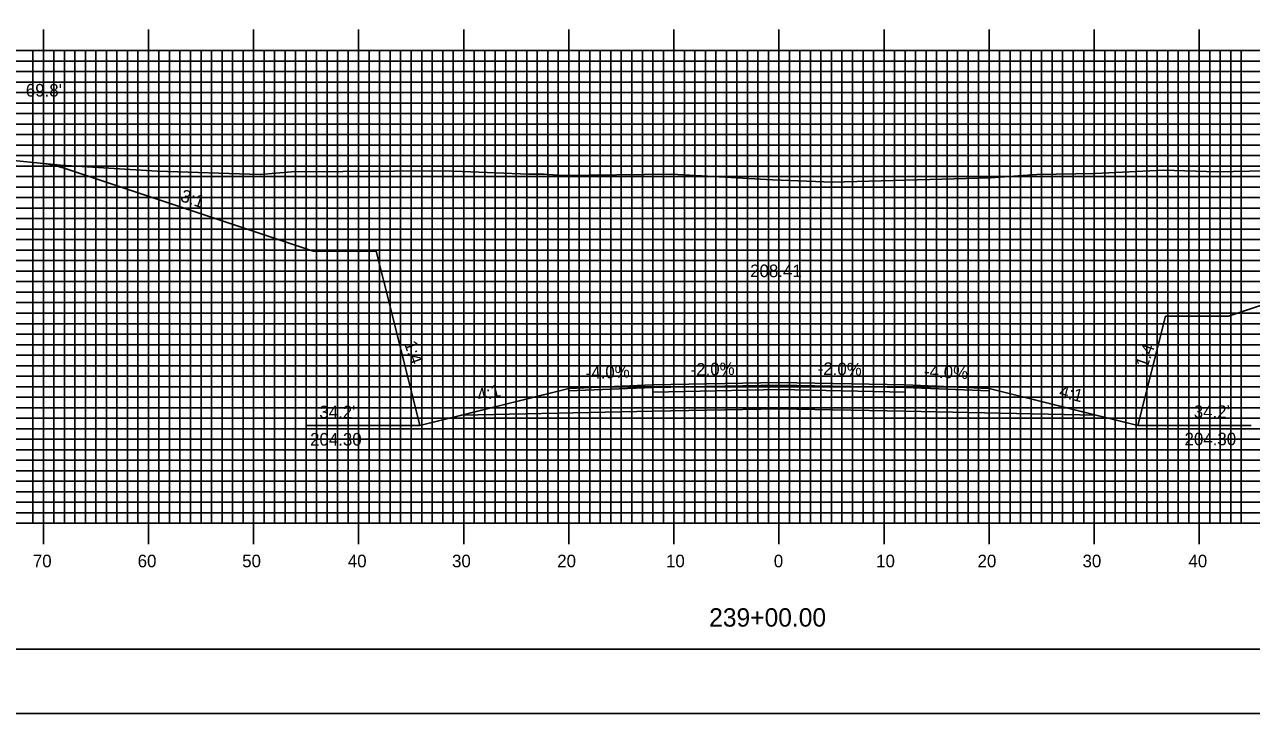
# Model space of a CAD drawing. Extents: x 1801536 to 1801879, y 442591 to 442811.
# Drawn here: x 1801629.8 to 1801746.5, y 442590.5 to 442656.2 of the extents above; entities that cross this region are included whole.
import ezdxf

# ---------------------------------------------------------------- set-up
doc = ezdxf.new("R2010")
doc.units = 0
for name, color, linetype in [('ANNOTATION', 7, 'Continuous'), ('BORDER', 7, 'Continuous'), ('D_Roadway_Centerline', 7, 'Continuous'), ('D_Roadway_Centerline_Text', 7, 'Continuous'), ('D_Roadway_Edge_Shoulder', 7, 'Continuous'), ('D_Roadway_Edge_TW', 7, 'Continuous'), ('D_Roadway_Pavement', 7, 'Continuous'), ('D_Roadway_SlopeLines', 7, 'Continuous'), ('D_Roadway_SubGrade', 7, 'Continuous'), ('D_Text_Standard', 7, 'Continuous'), ('H_V ANNOTATION', 7, 'Continuous'), ('MAJOR', 7, 'Continuous'), ('MINOR', 7, 'Continuous'), ('PDRAIN', 7, 'Continuous'), ('PLOT BOUNDARY', 7, 'Continuous'), ('S_Roadway_Centerline', 7, 'Continuous')]:
    doc.layers.add(name, color=color, linetype=linetype)

msp = doc.modelspace()

# ---------------------------------------------------------------- linework, layer by layer
at = {"layer": 'ANNOTATION'}
for p, q in [((1801735.75, 442617.97), (1801738.36, 442628.39)), ((1801738.36, 442628.39), (1801744.36, 442628.39))]:
    msp.add_line(p, q, dxfattribs=at)
at = {"layer": 'BORDER'}
msp.add_lwpolyline([(1801551.98, 442596.67), (1801871.98, 442596.67), (1801871.98, 442806.67), (1801551.98, 442806.67)], close=True, dxfattribs=at)
at = {"layer": 'D_Roadway_Centerline'}
msp.add_lwpolyline([(1801667.4, 442617.97), (1801671.4, 442618.97), (1801681.58, 442621.51), (1801689.58, 442621.83), (1801701.58, 442622.07), (1801713.58, 442621.83), (1801721.58, 442621.51), (1801731.75, 442618.97), (1801735.75, 442617.97)], dxfattribs=at)
at = {"layer": 'D_Roadway_Edge_Shoulder'}
for points in [[(1801689.58, 442621.83), (1801681.58, 442621.51), (1801681.58, 442621.26), (1801689.58, 442621.58)], [(1801713.58, 442621.83), (1801721.58, 442621.51), (1801721.58, 442621.26), (1801713.58, 442621.58)]]:
    msp.add_lwpolyline(points, close=True, dxfattribs=at)
at = {"layer": 'D_Roadway_Edge_TW'}
msp.add_lwpolyline([(1801689.58, 442621.58), (1801689.58, 442621.83), (1801701.58, 442622.07), (1801713.58, 442621.83), (1801713.58, 442621.58), (1801701.58, 442621.82)], close=True, dxfattribs=at)
at = {"layer": 'D_Roadway_Pavement'}
msp.add_lwpolyline([(1801689.58, 442621.16), (1801689.58, 442621.58), (1801701.58, 442621.82), (1801713.58, 442621.58), (1801713.58, 442621.16), (1801701.58, 442621.4)], close=True, dxfattribs=at)
at = {"layer": 'D_Roadway_SlopeLines'}
for p, q in [((1801781.97, 442640.93), (1801744.36, 442628.39)), ((1801667.4, 442617.97), (1801664.6, 442629.18))]:
    msp.add_line(p, q, dxfattribs=at)
for points in [[(1801664.6, 442629.18), (1801663.25, 442634.57), (1801657.25, 442634.57), (1801633.55, 442642.47)], [(1801681.58, 442621.51), (1801667.4, 442617.97)], [(1801721.58, 442621.51), (1801735.75, 442617.97)]]:
    msp.add_lwpolyline(points, dxfattribs=at)
msp.add_arc((1801629.88, 442631.45), 11.62, 71.5651, 80.3898, dxfattribs=at)
at = {"layer": 'D_Roadway_SubGrade'}
msp.add_lwpolyline([(1801689.58, 442619.33), (1801671.4, 442618.97), (1801681.58, 442621.51), (1801681.58, 442621.26), (1801689.58, 442621.58), (1801701.58, 442621.82), (1801713.58, 442621.58), (1801721.58, 442621.26), (1801721.58, 442621.51), (1801731.75, 442618.97), (1801713.58, 442619.33), (1801701.58, 442619.57)], close=True, dxfattribs=at)
at = {"layer": 'MAJOR'}
for p, q in [((1801631.58, 442655.67), (1801631.58, 442653.67)), ((1801641.58, 442655.67), (1801641.58, 442653.67)), ((1801651.58, 442655.67), (1801651.58, 442653.67)), ((1801661.58, 442655.67), (1801661.58, 442653.67)), ((1801671.58, 442655.67), (1801671.58, 442653.67)), ((1801681.58, 442655.67), (1801681.58, 442653.67)), ((1801691.58, 442655.67), (1801691.58, 442653.67)), ((1801701.58, 442655.67), (1801701.58, 442653.67)), ((1801711.58, 442655.67), (1801711.58, 442653.67)), ((1801721.58, 442655.67), (1801721.58, 442653.67)), ((1801731.58, 442655.67), (1801731.58, 442653.67)), ((1801741.58, 442655.67), (1801741.58, 442653.67)), ((1801561.58, 442653.67), (1801841.58, 442653.67)), ((1801561.58, 442653.67), (1801841.58, 442653.67)), ((1801631.58, 442608.67), (1801631.58, 442653.67)), ((1801641.58, 442608.67), (1801641.58, 442653.67)), ((1801651.58, 442608.67), (1801651.58, 442653.67)), ((1801661.58, 442608.67), (1801661.58, 442653.67)), ((1801671.58, 442608.67), (1801671.58, 442653.67)), ((1801681.58, 442608.67), (1801681.58, 442653.67)), ((1801691.58, 442608.67), (1801691.58, 442653.67)), ((1801701.58, 442608.67), (1801701.58, 442653.67)), ((1801711.58, 442608.67), (1801711.58, 442653.67)), ((1801721.58, 442608.67), (1801721.58, 442653.67)), ((1801731.58, 442608.67), (1801731.58, 442653.67)), ((1801741.58, 442608.67), (1801741.58, 442653.67)), ((1801561.58, 442648.67), (1801841.58, 442648.67)), ((1801561.58, 442643.67), (1801841.58, 442643.67)), ((1801561.58, 442638.67), (1801841.58, 442638.67)), ((1801561.58, 442633.67), (1801841.58, 442633.67)), ((1801561.58, 442628.67), (1801841.58, 442628.67)), ((1801561.58, 442623.67), (1801841.58, 442623.67)), ((1801561.58, 442618.67), (1801841.58, 442618.67)), ((1801561.58, 442613.67), (1801841.58, 442613.67)), ((1801561.58, 442608.67), (1801841.58, 442608.67)), ((1801561.58, 442608.67), (1801841.58, 442608.67)), ((1801631.58, 442606.66), (1801631.58, 442608.67)), ((1801641.58, 442606.66), (1801641.58, 442608.67)), ((1801651.58, 442606.66), (1801651.58, 442608.67)), ((1801661.58, 442606.66), (1801661.58, 442608.67)), ((1801671.58, 442606.66), (1801671.58, 442608.67)), ((1801681.58, 442606.66), (1801681.58, 442608.67)), ((1801691.58, 442606.66), (1801691.58, 442608.67)), ((1801701.58, 442606.66), (1801701.58, 442608.67)), ((1801711.58, 442606.66), (1801711.58, 442608.67)), ((1801721.58, 442606.66), (1801721.58, 442608.67)), ((1801731.58, 442606.66), (1801731.58, 442608.67)), ((1801741.58, 442606.66), (1801741.58, 442608.67))]:
    msp.add_line(p, q, dxfattribs=at)
at = {"layer": 'MINOR'}
for p, q in [((1801630.58, 442608.67), (1801630.58, 442653.67)), ((1801632.58, 442608.67), (1801632.58, 442653.67)), ((1801633.58, 442608.67), (1801633.58, 442653.67)), ((1801634.58, 442608.67), (1801634.58, 442653.67)), ((1801635.58, 442608.67), (1801635.58, 442653.67)), ((1801636.58, 442608.67), (1801636.58, 442653.67)), ((1801637.58, 442608.67), (1801637.58, 442653.67)), ((1801638.58, 442608.67), (1801638.58, 442653.67)), ((1801639.58, 442608.67), (1801639.58, 442653.67)), ((1801640.58, 442608.67), (1801640.58, 442653.67)), ((1801642.58, 442608.67), (1801642.58, 442653.67)), ((1801643.58, 442608.67), (1801643.58, 442653.67)), ((1801644.58, 442608.67), (1801644.58, 442653.67)), ((1801645.58, 442608.67), (1801645.58, 442653.67)), ((1801646.58, 442608.67), (1801646.58, 442653.67)), ((1801647.58, 442608.67), (1801647.58, 442653.67)), ((1801648.58, 442608.67), (1801648.58, 442653.67)), ((1801649.58, 442608.67), (1801649.58, 442653.67)), ((1801650.58, 442608.67), (1801650.58, 442653.67)), ((1801652.58, 442608.67), (1801652.58, 442653.67)), ((1801653.58, 442608.67), (1801653.58, 442653.67)), ((1801654.58, 442608.67), (1801654.58, 442653.67)), ((1801655.58, 442608.67), (1801655.58, 442653.67)), ((1801656.58, 442608.67), (1801656.58, 442653.67)), ((1801657.58, 442608.67), (1801657.58, 442653.67)), ((1801658.58, 442608.67), (1801658.58, 442653.67)), ((1801659.58, 442608.67), (1801659.58, 442653.67)), ((1801660.58, 442608.67), (1801660.58, 442653.67)), ((1801662.58, 442608.67), (1801662.58, 442653.67)), ((1801663.58, 442608.67), (1801663.58, 442653.67)), ((1801664.58, 442608.67), (1801664.58, 442653.67)), ((1801665.58, 442608.67), (1801665.58, 442653.67)), ((1801666.58, 442608.67), (1801666.58, 442653.67)), ((1801667.58, 442608.67), (1801667.58, 442653.67)), ((1801668.58, 442608.67), (1801668.58, 442653.67)), ((1801669.58, 442608.67), (1801669.58, 442653.67)), ((1801670.58, 442608.67), (1801670.58, 442653.67)), ((1801672.58, 442608.67), (1801672.58, 442653.67)), ((1801673.58, 442608.67), (1801673.58, 442653.67)), ((1801674.58, 442608.67), (1801674.58, 442653.67)), ((1801675.58, 442608.67), (1801675.58, 442653.67)), ((1801676.58, 442608.67), (1801676.58, 442653.67)), ((1801677.58, 442608.67), (1801677.58, 442653.67)), ((1801678.58, 442608.67), (1801678.58, 442653.67)), ((1801679.58, 442608.67), (1801679.58, 442653.67)), ((1801680.58, 442608.67), (1801680.58, 442653.67)), ((1801682.58, 442608.67), (1801682.58, 442653.67)), ((1801683.58, 442608.67), (1801683.58, 442653.67)), ((1801684.58, 442608.67), (1801684.58, 442653.67)), ((1801685.58, 442608.67), (1801685.58, 442653.67)), ((1801686.58, 442608.67), (1801686.58, 442653.67)), ((1801687.58, 442608.67), (1801687.58, 442653.67)), ((1801688.58, 442608.67), (1801688.58, 442653.67)), ((1801689.58, 442608.67), (1801689.58, 442653.67)), ((1801690.58, 442608.67), (1801690.58, 442653.67)), ((1801692.58, 442608.67), (1801692.58, 442653.67)), ((1801693.58, 442608.67), (1801693.58, 442653.67)), ((1801694.58, 442608.67), (1801694.58, 442653.67)), ((1801695.58, 442608.67), (1801695.58, 442653.67)), ((1801696.58, 442608.67), (1801696.58, 442653.67)), ((1801697.58, 442608.67), (1801697.58, 442653.67)), ((1801698.58, 442608.67), (1801698.58, 442653.67)), ((1801699.58, 442608.67), (1801699.58, 442653.67)), ((1801700.58, 442608.67), (1801700.58, 442653.67)), ((1801702.58, 442608.67), (1801702.58, 442653.67)), ((1801703.58, 442608.67), (1801703.58, 442653.67)), ((1801704.58, 442608.67), (1801704.58, 442653.67)), ((1801705.58, 442608.67), (1801705.58, 442653.67)), ((1801706.58, 442608.67), (1801706.58, 442653.67)), ((1801707.58, 442608.67), (1801707.58, 442653.67)), ((1801708.58, 442608.67), (1801708.58, 442653.67)), ((1801709.58, 442608.67), (1801709.58, 442653.67)), ((1801710.58, 442608.67), (1801710.58, 442653.67)), ((1801712.58, 442608.67), (1801712.58, 442653.67)), ((1801713.58, 442608.67), (1801713.58, 442653.67)), ((1801714.58, 442608.67), (1801714.58, 442653.67)), ((1801715.58, 442608.67), (1801715.58, 442653.67)), ((1801716.58, 442608.67), (1801716.58, 442653.67)), ((1801717.58, 442608.67), (1801717.58, 442653.67)), ((1801718.58, 442608.67), (1801718.58, 442653.67)), ((1801719.58, 442608.67), (1801719.58, 442653.67)), ((1801720.58, 442608.67), (1801720.58, 442653.67)), ((1801722.58, 442608.67), (1801722.58, 442653.67)), ((1801723.58, 442608.67), (1801723.58, 442653.67)), ((1801724.58, 442608.67), (1801724.58, 442653.67)), ((1801725.58, 442608.67), (1801725.58, 442653.67)), ((1801726.58, 442608.67), (1801726.58, 442653.67)), ((1801727.58, 442608.67), (1801727.58, 442653.67)), ((1801728.58, 442608.67), (1801728.58, 442653.67)), ((1801729.58, 442608.67), (1801729.58, 442653.67)), ((1801730.58, 442608.67), (1801730.58, 442653.67)), ((1801732.58, 442608.67), (1801732.58, 442653.67)), ((1801733.58, 442608.67), (1801733.58, 442653.67)), ((1801734.58, 442608.67), (1801734.58, 442653.67)), ((1801735.58, 442608.67), (1801735.58, 442653.67)), ((1801736.58, 442608.67), (1801736.58, 442653.67)), ((1801737.58, 442608.67), (1801737.58, 442653.67)), ((1801738.58, 442608.67), (1801738.58, 442653.67)), ((1801739.58, 442608.67), (1801739.58, 442653.67)), ((1801740.58, 442608.67), (1801740.58, 442653.67)), ((1801742.58, 442608.67), (1801742.58, 442653.67)), ((1801743.58, 442608.67), (1801743.58, 442653.67)), ((1801744.58, 442608.67), (1801744.58, 442653.67)), ((1801745.58, 442608.67), (1801745.58, 442653.67)), ((1801561.58, 442652.67), (1801841.58, 442652.67)), ((1801561.58, 442651.67), (1801841.58, 442651.67)), ((1801561.58, 442650.67), (1801841.58, 442650.67)), ((1801561.58, 442649.67), (1801841.58, 442649.67)), ((1801561.58, 442647.67), (1801841.58, 442647.67)), ((1801561.58, 442646.67), (1801841.58, 442646.67)), ((1801561.58, 442645.67), (1801841.58, 442645.67)), ((1801561.58, 442644.67), (1801841.58, 442644.67)), ((1801561.58, 442642.67), (1801841.58, 442642.67)), ((1801561.58, 442641.67), (1801841.58, 442641.67)), ((1801561.58, 442640.67), (1801841.58, 442640.67)), ((1801561.58, 442639.67), (1801841.58, 442639.67)), ((1801561.58, 442637.67), (1801841.58, 442637.67)), ((1801561.58, 442636.67), (1801841.58, 442636.67)), ((1801561.58, 442635.67), (1801841.58, 442635.67)), ((1801561.58, 442634.67), (1801841.58, 442634.67)), ((1801561.58, 442632.67), (1801841.58, 442632.67)), ((1801561.58, 442631.67), (1801841.58, 442631.67)), ((1801561.58, 442630.67), (1801841.58, 442630.67)), ((1801561.58, 442629.67), (1801841.58, 442629.67)), ((1801561.58, 442627.67), (1801841.58, 442627.67)), ((1801561.58, 442626.67), (1801841.58, 442626.67)), ((1801561.58, 442625.67), (1801841.58, 442625.67)), ((1801561.58, 442624.67), (1801841.58, 442624.67)), ((1801561.58, 442622.67), (1801841.58, 442622.67)), ((1801561.58, 442621.67), (1801841.58, 442621.67)), ((1801561.58, 442620.67), (1801841.58, 442620.67)), ((1801561.58, 442619.67), (1801841.58, 442619.67)), ((1801561.58, 442617.67), (1801841.58, 442617.67)), ((1801561.58, 442616.67), (1801841.58, 442616.67)), ((1801561.58, 442615.67), (1801841.58, 442615.67)), ((1801561.58, 442614.67), (1801841.58, 442614.67)), ((1801561.58, 442612.67), (1801841.58, 442612.67)), ((1801561.58, 442611.67), (1801841.58, 442611.67)), ((1801561.58, 442610.67), (1801841.58, 442610.67)), ((1801561.58, 442609.67), (1801841.58, 442609.67))]:
    msp.add_line(p, q, dxfattribs=at)
at = {"layer": 'PDRAIN'}
for p, q in [((1801656.68, 442617.97), (1801667.4, 442617.97)), ((1801735.75, 442617.97), (1801746.52, 442617.97))]:
    msp.add_line(p, q, dxfattribs=at)
at = {"layer": 'PLOT BOUNDARY'}
msp.add_lwpolyline([(1801535.79, 442590.55), (1801875.79, 442590.55), (1801875.79, 442810.55), (1801535.79, 442810.55)], close=True, dxfattribs=at)
at = {"layer": 'S_Roadway_Centerline'}
msp.add_lwpolyline([(1801625.82, 442643.48), (1801633.2, 442642.77), (1801642.41, 442642.2), (1801652.21, 442641.87), (1801655.19, 442642.14), (1801669.84, 442642.24), (1801677.77, 442641.91), (1801679.24, 442641.92), (1801680.88, 442641.77), (1801691.4, 442641.9), (1801700.96, 442641.36), (1801706.69, 442641.15), (1801721.7, 442641.55), (1801726.12, 442641.88), (1801731.66, 442641.97), (1801738.19, 442642.28), (1801743.29, 442642.13), (1801757.07, 442642.43)], dxfattribs=at)

# ---------------------------------------------------------------- texts
at = {"layer": 'ANNOTATION'}
for s, rotation, p in [('3:1', 341.5651, (1801644.54, 442639.36)), ('3:1', 341.5651, (1801644.54, 442639.36)), ('1:4', 289.484, (1801665.89, 442625.8)), ('1:4', 70.516, (1801736.62, 442623.38)), ('-2.0%', 1.1458, (1801693.18, 442622.7)), ('-2.0%', 358.8542, (1801705.26, 442622.8)), ('-4.0%', 2.2906, (1801683.21, 442622.38)), ('-4.0%', 357.7094, (1801715.37, 442622.56)), ('4:1', 14.0362, (1801673.02, 442620.23)), ('4:1', 345.9638, (1801728.17, 442620.72))]:
    msp.add_text(s, height=1.2, rotation=rotation, dxfattribs=at).set_placement(p)
for s, p in [("34.2'", (1801657.84, 442618.66)), ("34.2'", (1801741.06, 442618.69)), ('204.30', (1801656.96, 442616.06)), ('204.30', (1801740.18, 442616.09))]:
    msp.add_text(s, height=1.2, dxfattribs=at).set_placement(p)
at = {"layer": 'D_Roadway_Centerline'}
for s, p in [('C', (1801701.57, 442622.07)), ('L', (1801701.58, 442622.06))]:
    msp.add_text(s, height=0.0146, dxfattribs=at).set_placement(p)
at = {"layer": 'D_Roadway_Centerline_Text'}
msp.add_text('208.41', height=1.2, dxfattribs=at).set_placement((1801698.84, 442632.1))
at = {"layer": 'D_Text_Standard'}
msp.add_text("69.8'", height=1.2, dxfattribs=at).set_placement((1801629.91, 442649.3))
at = {"layer": 'H_V ANNOTATION'}
for s, height, p in [('70', 1.2, (1801630.58, 442604.47)), ('60', 1.2, (1801640.55, 442604.47)), ('50', 1.2, (1801650.5, 442604.47)), ('40', 1.2, (1801660.55, 442604.47)), ('30', 1.2, (1801670.47, 442604.47)), ('20', 1.2, (1801680.48, 442604.47)), ('10', 1.2, (1801690.83, 442604.47)), ('0', 1.2, (1801701.09, 442604.47)), ('10', 1.2, (1801710.83, 442604.47)), ('20', 1.2, (1801720.48, 442604.47)), ('30', 1.2, (1801730.47, 442604.47)), ('40', 1.2, (1801740.55, 442604.47)), ('239+00.00', 1.75, (1801694.94, 442598.82))]:
    msp.add_text(s, height=height, dxfattribs=at).set_placement(p)

doc.saveas('drawing.dxf')
